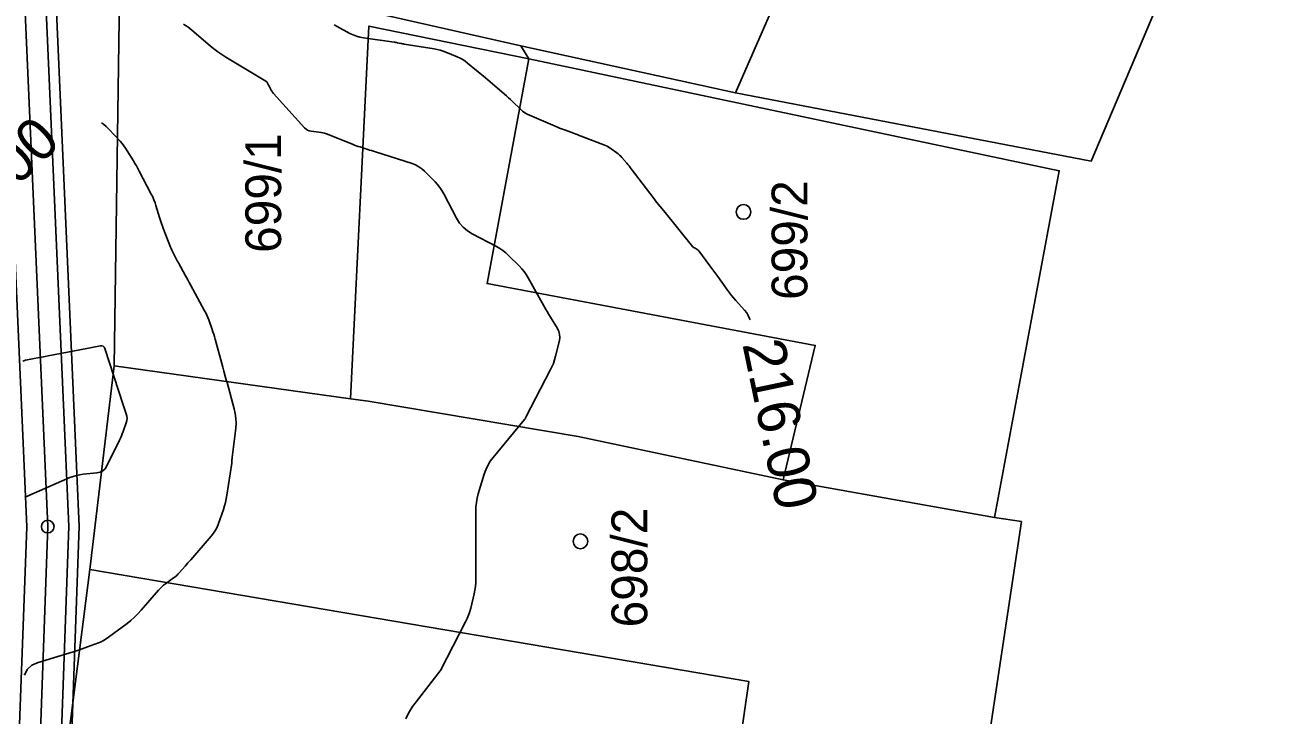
# Model space of a CAD drawing. Extents: x -534481 to -534256, y -1190577 to -1190138.
# Drawn here: x -534409.62 to -534379.97, y -1190413.9 to -1190397.49 of the extents above; entities that cross this region are included whole.
import ezdxf

# ---------------------------------------------------------------- set-up
doc = ezdxf.new("R2010")
doc.units = 0
for name, color, linetype in [('0_kroužky', 7, 'Continuous'), ('30', 7, 'Continuous'), ('31', 7, 'Continuous'), ('40', 7, 'Continuous'), ('_N_osa', 7, 'Continuous'), ('_tenka', 7, 'Continuous'), ('Hranice parcel', 7, 'Continuous'), ('Parcelní čísla', 7, 'Continuous'), ('Polygon budovy', 7, 'Continuous'), ('Značky budov', 7, 'Continuous')]:
    doc.layers.add(name, color=color, linetype=linetype)

msp = doc.modelspace()

# ---------------------------------------------------------------- linework, layer by layer
at = {"layer": '0_kroužky'}
msp.add_circle((-534409.076, -1190409.418), 0.15, dxfattribs=at)
msp.add_circle((-534409.076, -1190409.418), 0.15, dxfattribs=at)
msp.add_circle((-534409.076, -1190409.418), 0.15, dxfattribs=at)
msp.add_circle((-534409.076, -1190409.418), 0.15, dxfattribs=at)
msp.add_circle((-534409.076, -1190409.418), 0.15, dxfattribs=at)
msp.add_circle((-534409.076, -1190409.418), 0.15, dxfattribs=at)
at = {"layer": '30'}
for points in [[(-534392.381, -1190404.507), (-534392.392, -1190404.47), (-534392.421, -1190404.4), (-534392.46, -1190404.335), (-534392.509, -1190404.275), (-534392.72, -1190404.043), (-534392.771, -1190403.984), (-534392.822, -1190403.924), (-534392.87, -1190403.862), (-534392.917, -1190403.799), (-534393.15, -1190403.473), (-534393.196, -1190403.41), (-534393.242, -1190403.347), (-534393.288, -1190403.284), (-534393.335, -1190403.221), (-534393.6, -1190402.863), (-534393.608, -1190402.854), (-534393.616, -1190402.846), (-534393.625, -1190402.839), (-534393.634, -1190402.832), (-534393.682, -1190402.802), (-534393.694, -1190402.795), (-534393.706, -1190402.788), (-534393.731, -1190402.775), (-534393.737, -1190402.772), (-534393.742, -1190402.767), (-534393.747, -1190402.763), (-534393.752, -1190402.758), (-534394.433, -1190401.914), (-534394.517, -1190401.808), (-534394.601, -1190401.703), (-534394.684, -1190401.596), (-534394.766, -1190401.489), (-534395.203, -1190400.913), (-534395.23, -1190400.879), (-534395.257, -1190400.845), (-534395.284, -1190400.812), (-534395.312, -1190400.779), (-534395.428, -1190400.644), (-534395.455, -1190400.614), (-534395.484, -1190400.586), (-534395.514, -1190400.559), (-534395.546, -1190400.535), (-534395.678, -1190400.44), (-534395.711, -1190400.417), (-534395.746, -1190400.397), (-534395.781, -1190400.378), (-534395.819, -1190400.362), (-534396.394, -1190400.137), (-534396.44, -1190400.119), (-534396.487, -1190400.101), (-534396.534, -1190400.084), (-534396.581, -1190400.066), (-534396.768, -1190399.998), (-534396.815, -1190399.98), (-534396.861, -1190399.962), (-534396.908, -1190399.943), (-534396.954, -1190399.924), (-534397.622, -1190399.64), (-534397.681, -1190399.612), (-534397.736, -1190399.579), (-534397.789, -1190399.541), (-534397.838, -1190399.497), (-534398.027, -1190399.315), (-534398.075, -1190399.269), (-534398.123, -1190399.225), (-534398.172, -1190399.181), (-534398.221, -1190399.137), (-534398.451, -1190398.939), (-534398.506, -1190398.892), (-534398.561, -1190398.845), (-534398.616, -1190398.798), (-534398.672, -1190398.752), (-534399.095, -1190398.401), (-534399.152, -1190398.357), (-534399.212, -1190398.318), (-534399.275, -1190398.283), (-534399.341, -1190398.253), (-534399.609, -1190398.143), (-534399.677, -1190398.117), (-534399.745, -1190398.095), (-534399.815, -1190398.078), (-534399.886, -1190398.064), (-534400.606, -1190397.948), (-534400.626, -1190397.945), (-534400.646, -1190397.941), (-534400.666, -1190397.937), (-534400.686, -1190397.933), (-534400.765, -1190397.915), (-534400.785, -1190397.91), (-534400.804, -1190397.907), (-534400.824, -1190397.903), (-534400.844, -1190397.9), (-534401.573, -1190397.799), (-534401.657, -1190397.784), (-534401.738, -1190397.761), (-534401.817, -1190397.731), (-534401.894, -1190397.694), (-534402.195, -1190397.53), (-534402.27, -1190397.488)], [(-534407.8, -1190399.822), (-534407.753, -1190399.854), (-534407.685, -1190399.909), (-534407.623, -1190399.971), (-534407.358, -1190400.259), (-534407.311, -1190400.312), (-534407.267, -1190400.367), (-534407.226, -1190400.424), (-534407.188, -1190400.484), (-534407.04, -1190400.724), (-534407.004, -1190400.785), (-534406.968, -1190400.846), (-534406.934, -1190400.907), (-534406.901, -1190400.97), (-534406.614, -1190401.517), (-534406.582, -1190401.583), (-534406.553, -1190401.65), (-534406.526, -1190401.719), (-534406.504, -1190401.789), (-534406.418, -1190402.071), (-534406.396, -1190402.141), (-534406.373, -1190402.211), (-534406.348, -1190402.28), (-534406.322, -1190402.349), (-534406.155, -1190402.778), (-534406.141, -1190402.811), (-534406.127, -1190402.844), (-534406.112, -1190402.876), (-534406.095, -1190402.908), (-534406.029, -1190403.034), (-534406.012, -1190403.066), (-534405.996, -1190403.097), (-534405.979, -1190403.129), (-534405.961, -1190403.16), (-534405.806, -1190403.441), (-534405.775, -1190403.498), (-534405.743, -1190403.555), (-534405.712, -1190403.613), (-534405.681, -1190403.67), (-534405.347, -1190404.286), (-534405.32, -1190404.339), (-534405.294, -1190404.394), (-534405.271, -1190404.449), (-534405.25, -1190404.505), (-534405.17, -1190404.731), (-534405.151, -1190404.788), (-534405.132, -1190404.845), (-534405.115, -1190404.903), (-534405.098, -1190404.96), (-534404.914, -1190405.63), (-534404.889, -1190405.72), (-534404.847, -1190405.872), (-534404.831, -1190405.932), (-534404.814, -1190405.993), (-534404.643, -1190406.616), (-534404.617, -1190406.731), (-534404.603, -1190406.846), (-534404.6, -1190406.962), (-534404.609, -1190407.079), (-534404.694, -1190407.775), (-534404.695, -1190407.786), (-534404.696, -1190407.798), (-534404.696, -1190407.809), (-534404.697, -1190407.82), (-534404.698, -1190407.866), (-534404.699, -1190407.877), (-534404.699, -1190407.889), (-534404.701, -1190407.9), (-534404.702, -1190407.911), (-534404.817, -1190408.67), (-534404.832, -1190408.757), (-534404.851, -1190408.843), (-534404.874, -1190408.928), (-534404.901, -1190409.012), (-534405.016, -1190409.346), (-534405.049, -1190409.428), (-534405.089, -1190409.505), (-534405.136, -1190409.578), (-534405.19, -1190409.647), (-534405.678, -1190410.208), (-534405.711, -1190410.245), (-534405.743, -1190410.283), (-534405.776, -1190410.32), (-534405.809, -1190410.357), (-534405.941, -1190410.506), (-534405.975, -1190410.543), (-534406.01, -1190410.577), (-534406.048, -1190410.609), (-534406.087, -1190410.639), (-534406.279, -1190410.779), (-534406.323, -1190410.813), (-534406.366, -1190410.849), (-534406.405, -1190410.888), (-534406.443, -1190410.929), (-534406.856, -1190411.408), (-534406.933, -1190411.493), (-534407.014, -1190411.573), (-534407.1, -1190411.648), (-534407.19, -1190411.719), (-534407.632, -1190412.049), (-534407.689, -1190412.088), (-534407.748, -1190412.123), (-534407.809, -1190412.154), (-534407.872, -1190412.18), (-534408.13, -1190412.279), (-534408.195, -1190412.303), (-534408.26, -1190412.326), (-534408.325, -1190412.348), (-534408.391, -1190412.369), (-534409.301, -1190412.645), (-534409.454, -1190412.714), (-534409.564, -1190412.815), (-534409.631, -1190412.948)]]:
    msp.add_lwpolyline(points, dxfattribs=at)
at = {"layer": '31'}
for points in [[(-534400.561, -1190413.99), (-534400.493, -1190413.835), (-534400.398, -1190413.69), (-534399.744, -1190412.847), (-534399.74, -1190412.841), (-534399.142, -1190411.681), (-534399.105, -1190411.602), (-534399.072, -1190411.522), (-534399.044, -1190411.439), (-534399.022, -1190411.355), (-534398.941, -1190411.015), (-534398.923, -1190410.929), (-534398.911, -1190410.843), (-534398.903, -1190410.757), (-534398.901, -1190410.67), (-534398.901, -1190409.055), (-534398.897, -1190408.95), (-534398.886, -1190408.847), (-534398.867, -1190408.744), (-534398.841, -1190408.643), (-534398.702, -1190408.175), (-534398.664, -1190408.066), (-534398.616, -1190407.962), (-534398.557, -1190407.864), (-534398.488, -1190407.772), (-534397.746, -1190406.872), (-534397.743, -1190406.868), (-534397.739, -1190406.866), (-534397.732, -1190406.861), (-534397.729, -1190406.859), (-534397.727, -1190406.855), (-534397.721, -1190406.844), (-534397.72, -1190406.841), (-534397.711, -1190406.818), (-534397.707, -1190406.809), (-534397.703, -1190406.8), (-534397.129, -1190405.701), (-534397.09, -1190405.62), (-534397.056, -1190405.538), (-534397.027, -1190405.454), (-534397.004, -1190405.367), (-534396.914, -1190404.997), (-534396.903, -1190404.922), (-534396.907, -1190404.849), (-534396.926, -1190404.779), (-534396.96, -1190404.71), (-534397.124, -1190404.442), (-534397.165, -1190404.375), (-534397.205, -1190404.307), (-534397.245, -1190404.239), (-534397.284, -1190404.171), (-534397.656, -1190403.503), (-534397.702, -1190403.428), (-534397.753, -1190403.355), (-534397.808, -1190403.287), (-534397.869, -1190403.222), (-534398.121, -1190402.97), (-534398.186, -1190402.91), (-534398.255, -1190402.855), (-534398.328, -1190402.806), (-534398.405, -1190402.762), (-534398.985, -1190402.461), (-534399.101, -1190402.39), (-534399.202, -1190402.303), (-534399.288, -1190402.203), (-534399.36, -1190402.087), (-534399.661, -1190401.506), (-534399.705, -1190401.429), (-534399.754, -1190401.356), (-534399.809, -1190401.287), (-534399.869, -1190401.222), (-534400.121, -1190400.97), (-534400.186, -1190400.912), (-534400.258, -1190400.862), (-534400.334, -1190400.822), (-534400.416, -1190400.79), (-534401.288, -1190400.51), (-534401.334, -1190400.495), (-534401.379, -1190400.481), (-534401.425, -1190400.466), (-534401.47, -1190400.452), (-534401.652, -1190400.394), (-534401.697, -1190400.38), (-534401.743, -1190400.364), (-534401.787, -1190400.348), (-534401.832, -1190400.33), (-534402.451, -1190400.084), (-534402.495, -1190400.069), (-534402.539, -1190400.056), (-534402.584, -1190400.046), (-534402.63, -1190400.04), (-534402.814, -1190400.019), (-534402.859, -1190400.01), (-534402.899, -1190399.994), (-534402.936, -1190399.97), (-534402.969, -1190399.939), (-534403.713, -1190399.119), (-534403.727, -1190399.102), (-534403.741, -1190399.084), (-534403.753, -1190399.065), (-534403.764, -1190399.046), (-534403.814, -1190398.947), (-534403.825, -1190398.926), (-534403.836, -1190398.906), (-534403.858, -1190398.865), (-534403.864, -1190398.855), (-534403.872, -1190398.847), (-534403.88, -1190398.839), (-534403.889, -1190398.833), (-534404.84, -1190398.261), (-534404.938, -1190398.199), (-534405.034, -1190398.133), (-534405.126, -1190398.063), (-534405.215, -1190397.989), (-534405.648, -1190397.616), (-534405.696, -1190397.576), (-534405.747, -1190397.539), (-534405.799, -1190397.504), (-534405.852, -1190397.471)], [(-534409.671, -1190405.482), (-534409.608, -1190405.463), (-534409.27, -1190405.398), (-534409.134, -1190405.373), (-534409.067, -1190405.36), (-534408.151, -1190405.186), (-534407.988, -1190405.155), (-534407.825, -1190405.124), (-534407.787, -1190405.123), (-534407.757, -1190405.133), (-534407.734, -1190405.154), (-534407.717, -1190405.188), (-534407.28, -1190406.523), (-534407.209, -1190406.739), (-534407.196, -1190406.791), (-534407.192, -1190406.844), (-534407.197, -1190406.897), (-534407.211, -1190406.95), (-534407.285, -1190407.16), (-534407.305, -1190407.212), (-534407.325, -1190407.264), (-534407.348, -1190407.315), (-534407.371, -1190407.365), (-534407.671, -1190407.977), (-534407.713, -1190408.043), (-534407.766, -1190408.092), (-534407.831, -1190408.125), (-534407.907, -1190408.141), (-534408.235, -1190408.173), (-534408.316, -1190408.184), (-534408.396, -1190408.201), (-534408.474, -1190408.225), (-534408.55, -1190408.255), (-534409.595, -1190408.712), (-534409.609, -1190408.718), (-534409.623, -1190408.723)]]:
    msp.add_lwpolyline(points, dxfattribs=at)
at = {"layer": '_N_osa'}
msp.add_lwpolyline([(-534408.105, -1190518.46), (-534393.616, -1190502.389), (-534391.346, -1190496.962), (-534392.763, -1190488.017), (-534396.655, -1190477.752), (-534402.513, -1190464.283), (-534404.757, -1190456.741), (-534408.311, -1190433.088), (-534409.248, -1190427.879), (-534409.316, -1190416.054), (-534409.076, -1190409.418), (-534409.868, -1190391.439)], dxfattribs=at)
at = {"layer": '_tenka'}
for points in [[(-534405.057, -1190514.333), (-534394.044, -1190502.118), (-534391.862, -1190496.9), (-534393.249, -1190488.146), (-534397.118, -1190477.94), (-534402.983, -1190464.455), (-534405.247, -1190456.85), (-534408.804, -1190433.17), (-534409.748, -1190427.925), (-534409.816, -1190416.046), (-534409.577, -1190409.42), (-534410.397, -1190390.795)], [(-534403.656, -1190514.273), (-534393.187, -1190502.661), (-534390.83, -1190497.024), (-534392.278, -1190487.888), (-534396.191, -1190477.563), (-534402.042, -1190464.111), (-534404.268, -1190456.632), (-534407.818, -1190433.007), (-534408.749, -1190427.833), (-534408.816, -1190416.061), (-534408.576, -1190409.416), (-534409.363, -1190391.537)], [(-534403.306, -1190514.257), (-534392.973, -1190502.796), (-534390.572, -1190497.055), (-534392.035, -1190487.824), (-534395.96, -1190477.469), (-534401.807, -1190464.025), (-534404.023, -1190456.578), (-534407.571, -1190432.966), (-534408.499, -1190427.81), (-534408.566, -1190416.065), (-534408.326, -1190409.415), (-534409.111, -1190391.586)]]:
    msp.add_lwpolyline(points, dxfattribs=at)
at = {"layer": 'Hranice parcel'}
for p, q in [((-534407.5, -1190405.6), (-534407.36, -1190395.83)), ((-534407.36, -1190395.83), (-534397.83, -1190397.99)), ((-534397.83, -1190397.99), (-534397.64, -1190398.3)), ((-534407.5, -1190405.6), (-534401.88, -1190406.38))]:
    msp.add_line(p, q, dxfattribs=at)
for points in [[(-534397.83, -1190397.99), (-534392.73, -1190399.11), (-534384.27, -1190400.73), (-534379.97, -1190390.57)], [(-534401.88, -1190406.38), (-534401.44, -1190397.52), (-534397.64, -1190398.3)], [(-534397.64, -1190398.3), (-534385.03, -1190400.96), (-534386.57, -1190409.2)], [(-534408.57, -1190414.29), (-534408.08, -1190410.44), (-534407.5, -1190405.6)], [(-534386.57, -1190409.2), (-534391.59, -1190408.31), (-534396.47, -1190407.28), (-534401.46, -1190406.44), (-534401.88, -1190406.38)], [(-534386.57, -1190409.2), (-534385.93, -1190409.3), (-534387.24, -1190418.04)]]:
    msp.add_lwpolyline(points, dxfattribs=at)
at = {"layer": 'Polygon budovy'}
for points in [[(-534392.73, -1190399.11), (-534384.27, -1190400.73), (-534379.97, -1190390.57), (-534392.22, -1190385.07), (-534395.24, -1190392.02), (-534390.48, -1190393.97)], [(-534397.64, -1190398.3), (-534398.63, -1190403.64), (-534390.83, -1190405.11), (-534391.59, -1190408.31), (-534386.57, -1190409.2), (-534385.03, -1190400.96)], [(-534407.5, -1190405.6), (-534408.08, -1190410.44), (-534392.41, -1190413.1), (-534392.96, -1190416.94), (-534387.24, -1190418.04), (-534385.93, -1190409.3), (-534386.57, -1190409.2), (-534391.59, -1190408.31), (-534396.47, -1190407.28), (-534401.46, -1190406.44), (-534401.88, -1190406.38)]]:
    msp.add_lwpolyline(points, close=True, dxfattribs=at)
at = {"layer": 'Značky budov'}
for centre in [(-534392.536, -1190401.938), (-534396.412, -1190409.769)]:
    msp.add_circle(centre, 0.175, dxfattribs=at)

# ---------------------------------------------------------------- texts
at = {"layer": '40'}
for s, rotation, p in [('215.00', 43.7488, (-534411.684, -1190403.143)), ('216.00', 281.8324, (-534392.566, -1190405.077))]:
    msp.add_text(s, height=1, rotation=rotation, dxfattribs=at).set_placement(p)
at = {"layer": 'Parcelní čísla'}
for s, p in [('699/1', (-534403.529, -1190402.912)), ('699/2', (-534391.017, -1190404.03)), ('698/2', (-534394.824, -1190411.814))]:
    msp.add_text(s, height=0.85, rotation=90, dxfattribs=at).set_placement(p)

doc.saveas('drawing.dxf')
